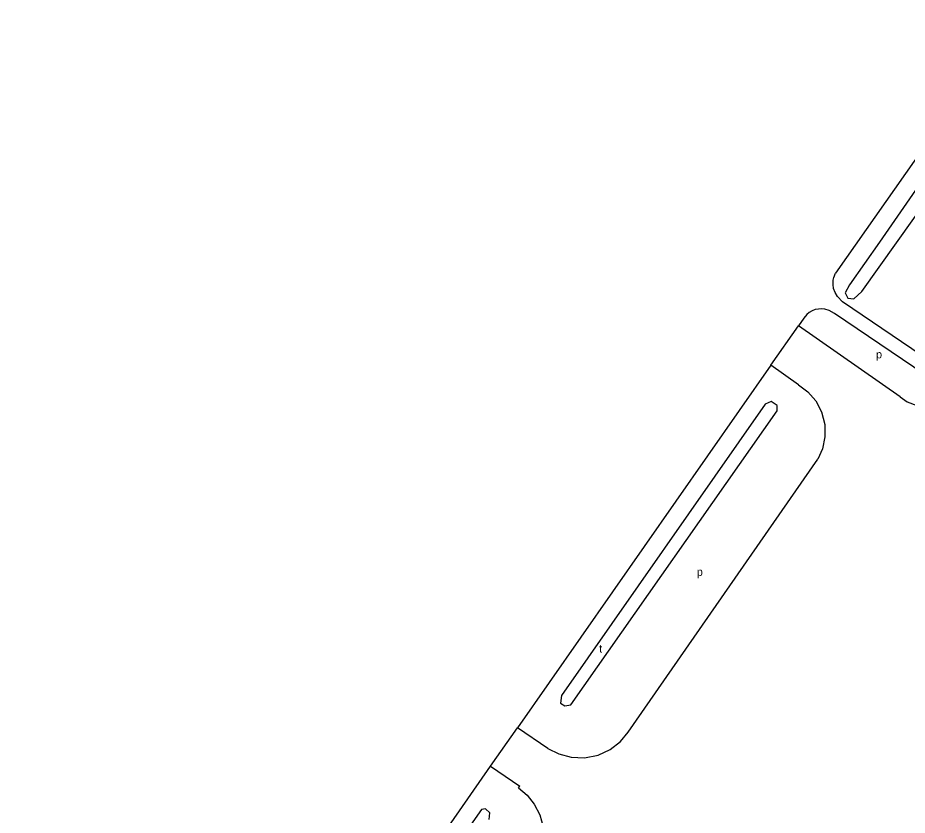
# Model space of a CAD drawing. Extents: x 154765 to 156627, y 383996 to 386132.
# Drawn here: x 154765.6 to 155210.2, y 385414.8 to 385813.4 of the extents above; entities that cross this region are included whole.
import ezdxf

# ---------------------------------------------------------------- set-up
doc = ezdxf.new("R2010")
doc.units = 0
for name, color, linetype in [('BLT_Basislijn', 7, 'Continuous'), ('BLT_Centroide', 7, 'Continuous'), ('BLT_Vlakafsluiter', 7, 'Continuous')]:
    doc.layers.add(name, color=color, linetype=linetype)

msp = doc.modelspace()

# ---------------------------------------------------------------- linework, layer by layer
at = {"layer": 'BLT_Basislijn'}
for p, q in [((155206.7, 385623.89), (155155.85, 385659.41)), ((155142.06, 385639.71), (155015.35, 385458.57)), ((155155.96, 385629.93), (155142.06, 385639.71)), ((155070.73, 385456.41), (155165.51, 385592.82)), ((155030.66, 385448.25), (155015.35, 385458.57)), ((155001.95, 385439.41), (155016.62, 385429.43)), ((155015.95, 385428.47), (155016.62, 385429.43))]:
    msp.add_line(p, q, dxfattribs=at)
for points in [[(155263.99, 385813.43), (155174.31, 385685.7)], [(155251.92, 385621.3), (155177.96, 385671.49), (155175.35, 385674.07), (155174.17, 385676.1), (155173.46, 385678.13), (155173.17, 385680.09), (155173.16, 385682.3), (155173.51, 385683.65), (155174.31, 385685.7)], [(155241.85, 385619.55), (155173.97, 385665.6), (155171.25, 385667.04), (155169.08, 385667.7), (155167.41, 385667.89), (155165.87, 385667.85), (155164.26, 385667.57), (155162.8, 385667.03), (155161.24, 385666.07), (155160.08, 385665.07), (155158.61, 385663.34)], [(155158.61, 385663.34), (155155.85, 385659.41)], [(155155.96, 385629.93), (155160.52, 385626.54), (155164.49, 385621.97), (155167.44, 385616.4), (155169.03, 385610.21), (155169.14, 385603.91), (155167.87, 385597.99), (155165.51, 385592.82)], [(155206.7, 385623.89), (155210.27, 385621.44), (155215.01, 385619.67), (155217.62, 385619.04), (155220.38, 385618.79), (155241.06, 385619.41), (155241.85, 385619.55)], [(155030.66, 385448.25), (155036.04, 385445.45), (155042.28, 385443.78), (155049, 385443.55), (155055.69, 385444.91), (155061.78, 385447.75), (155066.87, 385451.73), (155070.73, 385456.41)], [(154765.62, 385101.6), (154839.26, 385204.33), (154900.05, 385293.83), (154915.63, 385315.65), (154956.88, 385374.58), (155001.95, 385439.41)], [(155015.95, 385428.47), (155020.19, 385424.88), (155023.84, 385420.32), (155026.58, 385414.96), (155028.2, 385409.1), (155028.58, 385403.09), (155027.78, 385397.3), (155025.98, 385392.05)], [(155001.32, 385412.67), (155001.59, 385415.96), (154999.49, 385418.06), (154997.48, 385417.61), (154946.23, 385344.88)]]:
    msp.add_lwpolyline(points, dxfattribs=at)
for points in [[(155251.17, 385779.48), (155244.4, 385770.54), (155196.32, 385701.19), (155181.42, 385679.93), (155179.25, 385676), (155180.61, 385673.29), (155183.59, 385672.89), (155187.52, 385676.68), (155247.38, 385760.52), (155256.46, 385774.33), (155255.51, 385777.99), (155252.66, 385779.75)], [(155139.2, 385620.26), (155037.35, 385474.67), (155036.96, 385470.83), (155039.07, 385469.49), (155042.14, 385470.07), (155145.15, 385617), (155145.15, 385619.68), (155142.27, 385621.6)]]:
    msp.add_lwpolyline(points, close=True, dxfattribs=at)
at = {"layer": 'BLT_Vlakafsluiter'}
for p, q in [((155142.06, 385639.71), (155155.85, 385659.41)), ((155001.95, 385439.41), (155015.35, 385458.57))]:
    msp.add_line(p, q, dxfattribs=at)

# ---------------------------------------------------------------- texts
at = {"layer": 'BLT_Centroide'}
for s, p in [('p', (155194.67, 385643.2)), ('p', (155105.08, 385534.47)), ('t', (155056.24, 385496.13))]:
    msp.add_text(s, height=4, dxfattribs=at).set_placement(p)

doc.saveas('drawing.dxf')
